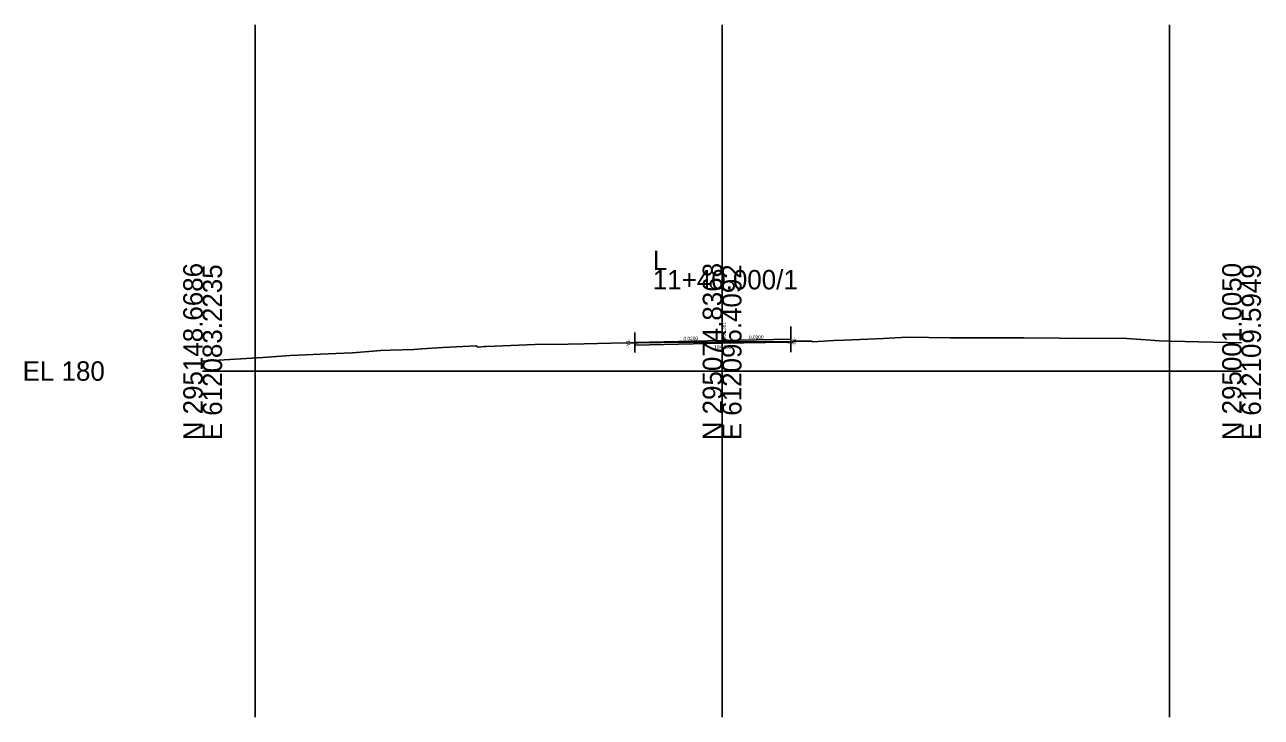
# Model space of a CAD drawing. Extents: x -81 to 616364, y 450 to 299952.
# Drawn here: x 535426.7 to 535605.2, y 118298.4 to 118398.4 of the extents above; entities that cross this region are included whole.
import ezdxf

# ---------------------------------------------------------------- set-up
doc = ezdxf.new("R2010")
doc.units = 0
for name, color, linetype in [('Exist XS Ground Line', 7, 'Continuous'), ('Old_Level_6', 7, 'Continuous'), ('Old_Level_63', 7, 'Continuous'), ('Prop XS Dump Level', 7, 'Continuous'), ('Prop XS Earthwork Shape', 7, 'Continuous'), ('Prop XS EOT Tick Mark', 7, 'Continuous'), ('Prop XS Exc Vertical Line 1', 7, 'Continuous'), ('Prop XS Exc Vertical Line 2', 7, 'Continuous'), ('Prop XS Exc Vertical Line 3', 7, 'Continuous'), ('Prop XS Finish Grade Pavement', 7, 'Continuous'), ('Prop XS Side Slope Text', 7, 'Continuous'), ('Prop XS Subgrade Concrete', 7, 'Continuous'), ('Prop XS Subgrade Earthwork', 7, 'Continuous')]:
    doc.layers.add(name, color=color, linetype=linetype)

msp = doc.modelspace()

# ---------------------------------------------------------------- linework, layer by layer
at = {"layer": 'Exist XS Ground Line'}
msp.add_lwpolyline([(535452.36, 118349.77), (535453.89, 118349.87), (535461.05, 118350.31), (535465.02, 118350.59), (535471.58, 118350.88), (535473.99, 118351.01), (535477.51, 118351.27), (535478.04, 118351.31), (535479.49, 118351.37), (535482.87, 118351.48), (535483.99, 118351.56), (535487.04, 118351.75), (535491.83, 118351.98), (535491.99, 118351.9), (535492.13, 118351.83), (535493.04, 118351.89), (535493.29, 118351.91), (535495.72, 118351.99), (535500.34, 118352.17), (535505.12, 118352.26), (535507.45, 118352.31), (535511.34, 118352.39), (535514.14, 118352.44), (535515.25, 118352.45), (535516.03, 118352.46), (535518.63, 118352.48), (535526.72, 118352.54), (535527.36, 118352.56), (535527.71, 118352.56), (535532.3, 118352.57), (535533.18, 118352.58), (535534.26, 118352.58), (535536.76, 118352.57), (535536.86, 118352.56), (535537.49, 118352.54), (535537.66, 118352.69), (535539.18, 118352.67), (535540.28, 118352.69), (535540.46, 118352.59), (535543.47, 118352.76), (535544.97, 118352.84), (535550.64, 118353.05), (535554.1, 118353.23), (535560.3, 118353.15), (535560.94, 118353.16), (535561.08, 118353.15), (535565.34, 118353.13), (535568.7, 118353.15), (535570.94, 118353.15), (535576.05, 118353.12), (535578.98, 118353.08), (535585.08, 118353.09), (535588.6, 118352.88), (535590.45, 118352.73), (535592.08, 118352.66), (535602.36, 118352.45)], dxfattribs=at)
at = {"layer": 'Old_Level_6'}
for p, q in [((535514.76, 118351.02), (535514.76, 118353.93)), ((535537.26, 118351.07), (535537.26, 118354.78))]:
    msp.add_line(p, q, dxfattribs=at)
at = {"layer": 'Old_Level_63'}
for p, q in [((535527.36, 118348.36), (535527.36, 118362.95)), ((535452.36, 118348.36), (535527.36, 118348.36)), ((535527.36, 118348.36), (535602.36, 118348.36))]:
    msp.add_line(p, q, dxfattribs=at)
at = {"layer": 'Prop XS Dump Level'}
for p, q in [((535514.76, 118352.49), (535527.36, 118352.75)), ((535527.36, 118352.75), (535537.26, 118352.94))]:
    msp.add_line(p, q, dxfattribs=at)
at = {"layer": 'Prop XS Earthwork Shape'}
for points in [[(535536.77, 118352.55), (535536.77, 118352.57), (535536.76, 118352.57), (535534.26, 118352.58), (535533.18, 118352.58), (535532.3, 118352.57), (535527.71, 118352.56), (535527.36, 118352.56), (535526.72, 118352.54), (535518.63, 118352.48), (535516.03, 118352.46), (535515.25, 118352.45), (535514.76, 118352.45), (535514.76, 118352.11), (535527.36, 118352.37)], [(535514.76, 118352.45), (535515.25, 118352.45), (535516.03, 118352.46), (535518.63, 118352.48), (535526.72, 118352.54), (535527.36, 118352.56), (535527.71, 118352.56), (535532.3, 118352.57), (535533.18, 118352.58), (535534.26, 118352.58), (535536.76, 118352.57), (535536.77, 118352.57), (535536.77, 118352.55), (535527.36, 118352.37), (535514.76, 118352.11)], [(535514.76, 118352.45), (535515.25, 118352.45), (535516.03, 118352.46), (535518.63, 118352.48), (535526.72, 118352.54), (535527.36, 118352.56), (535527.71, 118352.56), (535532.3, 118352.57), (535533.18, 118352.58), (535534.26, 118352.58), (535536.76, 118352.57), (535536.77, 118352.57), (535536.77, 118352.55), (535527.36, 118352.37), (535514.76, 118352.11)], [(535514.76, 118352.45), (535515.25, 118352.45), (535516.03, 118352.46), (535518.63, 118352.48), (535526.72, 118352.54), (535527.36, 118352.56), (535527.71, 118352.56), (535532.3, 118352.57), (535533.18, 118352.58), (535534.26, 118352.58), (535536.77, 118352.55), (535527.36, 118352.37), (535514.76, 118352.11)], [(535514.76, 118352.11), (535514.76, 118352.45), (535515.25, 118352.45), (535516.03, 118352.46), (535518.63, 118352.48), (535526.72, 118352.54), (535527.36, 118352.56), (535527.71, 118352.56), (535532.3, 118352.57), (535533.18, 118352.58), (535534.26, 118352.58), (535536.76, 118352.57), (535536.86, 118352.56), (535536.97, 118352.56), (535536.77, 118352.55), (535527.36, 118352.37)], [(535514.76, 118352.11), (535514.76, 118352.45), (535515.25, 118352.45), (535516.03, 118352.46), (535518.63, 118352.48), (535526.72, 118352.54), (535527.36, 118352.56), (535527.71, 118352.56), (535532.3, 118352.57), (535533.18, 118352.58), (535534.26, 118352.58), (535536.76, 118352.57), (535536.86, 118352.56), (535536.97, 118352.56), (535536.77, 118352.55), (535527.36, 118352.37)], [(535514.76, 118352.11), (535527.36, 118352.37), (535527.36, 118352.56), (535526.72, 118352.54), (535518.63, 118352.48), (535516.03, 118352.46), (535515.25, 118352.45), (535514.76, 118352.45)], [(535527.36, 118352.37), (535536.77, 118352.55), (535536.97, 118352.56), (535536.86, 118352.56), (535536.76, 118352.57), (535534.26, 118352.58), (535533.18, 118352.58), (535532.3, 118352.57), (535527.71, 118352.56), (535527.36, 118352.56)], [(535536.77, 118352.57), (535536.86, 118352.56), (535536.97, 118352.56), (535536.77, 118352.55)], [(535536.77, 118352.57), (535536.77, 118352.55), (535536.97, 118352.56), (535536.86, 118352.56)], [(535536.77, 118352.57), (535536.77, 118352.55), (535536.97, 118352.56), (535536.86, 118352.56)], [(535536.86, 118352.56), (535536.97, 118352.56), (535536.77, 118352.55)], [(535537.26, 118352.56), (535537.26, 118352.55), (535536.97, 118352.56)], [(535536.97, 118352.56), (535537.26, 118352.55), (535537.26, 118352.56)], [(535536.97, 118352.56), (535537.26, 118352.55), (535537.26, 118352.56)]]:
    msp.add_lwpolyline(points, close=True, dxfattribs=at)
at = {"layer": 'Prop XS EOT Tick Mark'}
msp.add_line((535537.26, 118352.94), (535537.26, 118353.25), dxfattribs=at)
at = {"layer": 'Prop XS Exc Vertical Line 1'}
msp.add_line((535459.94, 118398.36), (535459.94, 118298.36), dxfattribs=at)
at = {"layer": 'Prop XS Exc Vertical Line 2'}
msp.add_line((535527.36, 118398.36), (535527.36, 118298.36), dxfattribs=at)
at = {"layer": 'Prop XS Exc Vertical Line 3'}
msp.add_line((535591.96, 118398.36), (535591.96, 118298.36), dxfattribs=at)
at = {"layer": 'Prop XS Finish Grade Pavement'}
for p, q in [((535527.36, 118352.75), (535514.76, 118352.49)), ((535537.26, 118352.94), (535527.36, 118352.75))]:
    msp.add_line(p, q, dxfattribs=at)
at = {"layer": 'Prop XS Subgrade Concrete'}
msp.add_line((535537.26, 118352.94), (535537.26, 118352.76), dxfattribs=at)
at = {"layer": 'Prop XS Subgrade Earthwork'}
for p, q in [((535514.76, 118352.11), (535514.76, 118352.45)), ((535514.76, 118352.11), (535527.36, 118352.37)), ((535527.36, 118352.37), (535536.77, 118352.55)), ((535536.77, 118352.55), (535536.97, 118352.56))]:
    msp.add_line(p, q, dxfattribs=at)

# ---------------------------------------------------------------- texts
at = {"layer": 'Old_Level_63'}
for s, p in [('L', (535517.36, 118362.95)), ('11+40.000/1', (535517.36, 118360.15)), ('EL 180', (535426.37, 118346.96))]:
    msp.add_text(s, height=2.8, dxfattribs=at).set_placement(p)
for s, p in [('N 295148.6686', (535452.36, 118338.36)), ('E 612083.2235', (535455.16, 118338.36)), ('N 295074.8368', (535527.36, 118338.36)), ('E 612096.4092', (535530.16, 118338.37)), ('N 295001.0050', (535602.36, 118338.36)), ('E 612109.5949', (535605.16, 118338.37))]:
    msp.add_text(s, height=2.8, rotation=90, dxfattribs=at).set_placement(p)
at = {"layer": 'Prop XS Dump Level'}
msp.add_text('Eop', height=0.3, dxfattribs=at).set_placement((535536.77, 118352.27))
msp.add_text('Eop', height=0.3, dxfattribs=at).set_placement((535536.77, 118352.27))
at = {"layer": 'Prop XS Side Slope Text'}
for s, rotation, p in [(' 184.381', 90, (535527.86, 118352.75)), ('-Y1-', 90, (535514.05, 118351.7)), ('0.0200', 1.1458, (535521.79, 118352.79)), ('0.0200', 1.1458, (535531.24, 118352.98)), ('-Y2-', 90, (535538.01, 118351.95))]:
    msp.add_text(s, height=0.5, rotation=rotation, dxfattribs=at).set_placement(p)
msp.add_text('184.192', height=0.5, dxfattribs=at).set_placement((535526.23, 118351.58))

doc.saveas('drawing.dxf')
